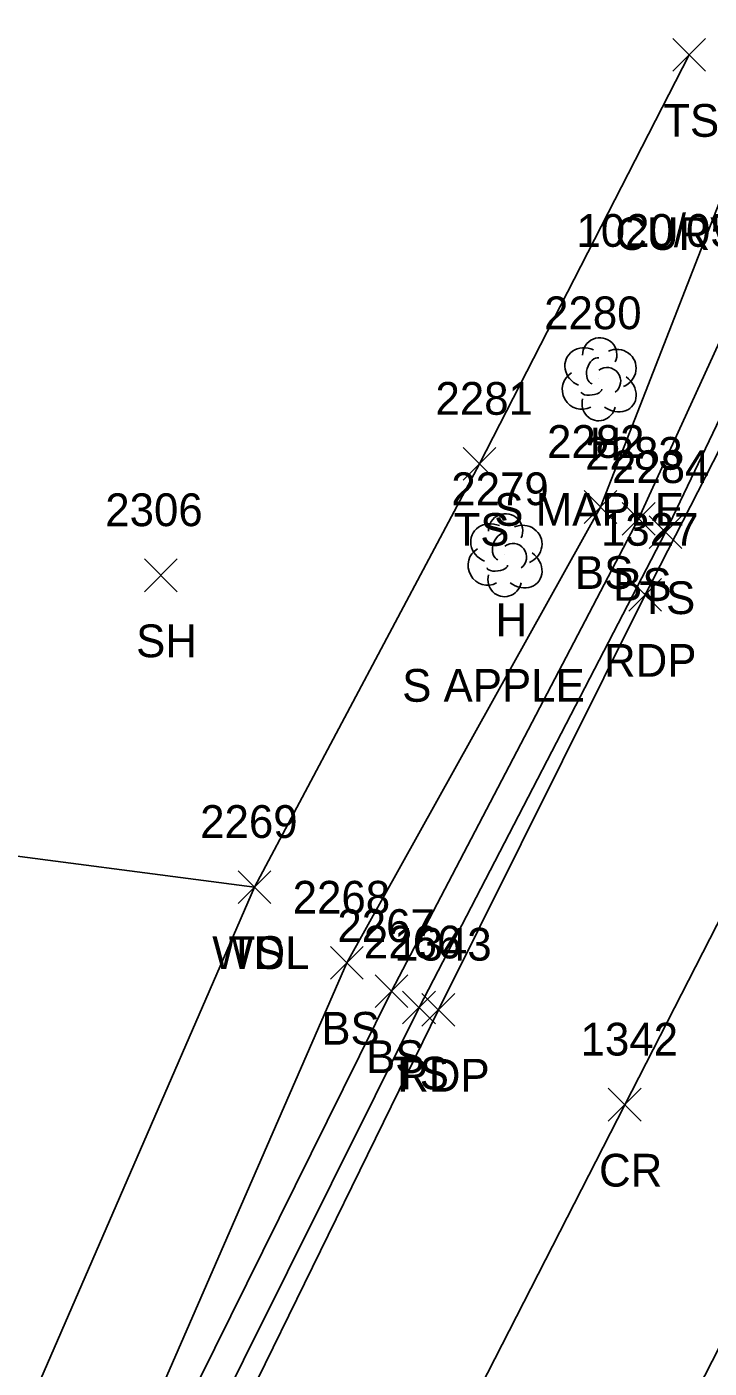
# Model space of a CAD drawing. Extents: x 1885914 to 1887218, y 756253 to 760620.
# Drawn here: x 1886645.8 to 1886687.5, y 760277.1 to 760359 of the extents above; entities that cross this region are included whole.
import ezdxf

# ---------------------------------------------------------------- set-up
doc = ezdxf.new("R2010")
doc.units = 0
for name, color, linetype in [('L_A', 7, 'Continuous'), ('L_C', 7, 'Continuous'), ('L_I', 7, 'Continuous'), ('L_TIC', 7, 'Continuous'), ('LAWA', 7, 'Continuous'), ('LELB', 7, 'Continuous'), ('LTD', 7, 'Continuous'), ('P_A', 7, 'Continuous'), ('P_I', 7, 'Continuous'), ('P_TIC', 7, 'Continuous'), ('PET', 7, 'Continuous'), ('PRC', 7, 'Continuous'), ('S_C', 7, 'Continuous')]:
    doc.layers.add(name, color=color, linetype=linetype)

msp = doc.modelspace()

# ---------------------------------------------------------------- linework, layer by layer
at = {"layer": 'L_TIC'}
for points in [[(1886685.242, 760356.287), (1886687.242, 760358.287)], [(1886687.242, 760356.287), (1886685.242, 760358.287)], [(1886672.438, 760331.318), (1886674.438, 760333.318)], [(1886674.438, 760331.318), (1886672.438, 760333.318)], [(1886679.817, 760328.686), (1886681.817, 760330.686)], [(1886681.817, 760328.686), (1886679.817, 760330.686)], [(1886682.151, 760327.963), (1886684.151, 760329.963)], [(1886684.151, 760327.963), (1886682.151, 760329.963)], [(1886683.784, 760327.15), (1886685.784, 760329.15)], [(1886685.784, 760327.15), (1886683.784, 760329.15)], [(1886652.974, 760324.518), (1886654.974, 760326.518)], [(1886654.974, 760324.518), (1886652.974, 760326.518)], [(1886658.691, 760305.487), (1886660.691, 760307.487)], [(1886660.691, 760305.487), (1886658.691, 760307.487)], [(1886658.691, 760305.487), (1886660.691, 760307.487)], [(1886660.691, 760305.487), (1886658.691, 760307.487)], [(1886664.332, 760300.863), (1886666.332, 760302.863)], [(1886666.332, 760300.863), (1886664.332, 760302.863)], [(1886667.061, 760299.134), (1886669.061, 760301.134)], [(1886669.061, 760299.134), (1886667.061, 760301.134)], [(1886668.739, 760298.131), (1886670.739, 760300.131)], [(1886670.739, 760298.131), (1886668.739, 760300.131)]]:
    msp.add_lwpolyline(points, dxfattribs=at)
at = {"layer": 'LAWA'}
msp.add_lwpolyline([(1886557.492, 760303.875), (1886591.462, 760287.384), (1886586.596, 760261.317), (1886572.395, 760231.508), (1886560.835, 760204.169), (1886553.529, 760184.951), (1886554.608, 760165.788), (1886555.431, 760150.16), (1886559.733, 760135.931), (1886571.707, 760133.875), (1886584.515, 760154.184), (1886595.308, 760177.701), (1886612.547, 760208.5), (1886627.728, 760237.63), (1886641.554, 760264.816), (1886659.691, 760306.487), (1886641.283, 760308.875), (1886618.53, 760315.267), (1886578.462, 760328.998), (1886533.456, 760348.84), (1886508.343, 760359.001)], dxfattribs=at)
at = {"layer": 'LELB'}
for points in [[(1886659.691, 760306.487), (1886673.438, 760332.318), (1886686.242, 760357.287)], [(1886566.147, 760118.03), (1886586.712, 760153.389), (1886597.757, 760175.933), (1886614.926, 760207.48), (1886633.427, 760234.813), (1886648.397, 760263.018), (1886665.332, 760301.863), (1886680.817, 760329.686), (1886690.647, 760354.868)], [(1886569.485, 760114.599), (1886588.518, 760152.373), (1886601.13, 760173.249), (1886619.202, 760206.038), (1886634.532, 760234.244), (1886649.403, 760262.458), (1886668.061, 760300.134), (1886683.151, 760328.963), (1886694.248, 760353.247)], [(1886571.834, 760112.637), (1886591.916, 760150.851), (1886603.315, 760171.698), (1886621.882, 760204.85), (1886636.208, 760233.059), (1886650.971, 760261.462), (1886669.739, 760299.131), (1886684.784, 760328.15), (1886696.366, 760352.364)]]:
    msp.add_lwpolyline(points, dxfattribs=at)
at = {"layer": 'LTD'}
for p, q in [((1886680.727, 760337.541), (1886680.727, 760337.541)), ((1886680.727, 760337.541), (1886680.727, 760337.541)), ((1886674.979, 760326.8), (1886674.979, 760326.8)), ((1886674.979, 760326.8), (1886674.979, 760326.8))]:
    msp.add_line(p, q, dxfattribs=at)
for centre in [(1886680.774, 760338.975), (1886675.025, 760328.234)]:
    msp.add_arc(centre, 1.047, 335.52715, 180.95627, dxfattribs=at)
for centre, major_axis, ratio, start_param, end_param in [((1886679.935, 760338.207), (1.21, -0.512), 0.895232, 1.570796, 4.712389), ((1886680.518, 760337.999), (-0.208, -0.792), 0.645439, 3.141593, 6.283185), ((1886681.768, 760338.124), (-1.141, -0.483), 0.949671, 1.570796, 4.712389), ((1886681.227, 760337.374), (-0.5, 0.667), 0.989748, 3.141593, 6.283185), ((1886679.644, 760336.832), (0.584, -1.042), 0.959034, 3.141593, 6.283185), ((1886681.727, 760336.708), (-1.09, 0.792), 0.841452, 1.570796, 4.712389), ((1886680.727, 760336.041), (0.265, 1.061), 0.942809, 1.570796, 4.712389), ((1886680.269, 760336.791), (-0.625, -0.083), 0.423636, 0, 3.141593), ((1886674.187, 760327.467), (1.21, -0.512), 0.895232, 1.570796, 4.712389), ((1886674.77, 760327.259), (-0.208, -0.792), 0.645439, 3.141593, 6.283185), ((1886676.02, 760327.384), (-1.141, -0.483), 0.949671, 1.570796, 4.712389), ((1886675.479, 760326.634), (-0.5, 0.667), 0.989748, 3.141593, 6.283185), ((1886673.895, 760326.092), (0.584, -1.042), 0.959034, 3.141593, 6.283185), ((1886675.979, 760325.967), (-1.09, 0.792), 0.841452, 1.570796, 4.712389), ((1886674.52, 760326.05), (-0.625, -0.083), 0.423636, 0, 3.141593), ((1886674.979, 760325.3), (0.265, 1.061), 0.942809, 1.570796, 4.712389)]:
    msp.add_ellipse(centre, major_axis=major_axis, ratio=ratio, start_param=start_param, end_param=end_param, dxfattribs=at)
at = {"layer": 'P_TIC'}
for points in [[(1886682.548, 760323.324), (1886684.548, 760325.324)], [(1886684.548, 760323.324), (1886682.548, 760325.324)], [(1886669.919, 760297.997), (1886671.919, 760299.997)], [(1886671.919, 760297.997), (1886669.919, 760299.997)], [(1886681.3, 760292.202), (1886683.3, 760294.202)], [(1886683.3, 760292.202), (1886681.3, 760294.202)]]:
    msp.add_lwpolyline(points, dxfattribs=at)
at = {"layer": 'PET'}
for points in [[(1886697.38, 760351.344), (1886683.548, 760324.324), (1886670.919, 760298.997), (1886655.54, 760267.572), (1886637.844, 760233.454), (1886621.762, 760202.258), (1886604.958, 760170.918), (1886588.135, 760139.085), (1886573.727, 760111.629), (1886569.921, 760108.658), (1886558.783, 760086.235), (1886539.061, 760048.095), (1886537.996, 760043.117), (1886529.578, 760026.839), (1886519.947, 760007.47), (1886505.21, 759975.038), (1886485.323, 759931.758)], [(1886719.61, 760339.514), (1886705.929, 760312.964), (1886693.411, 760288.801), (1886676.565, 760255.91), (1886659.381, 760222.808), (1886642.609, 760189.876), (1886625.619, 760158.68), (1886608.905, 760127.1), (1886594.007, 760097.907), (1886581.162, 760073.399), (1886568.003, 760045.025), (1886556.596, 760025.444), (1886542.605, 759998.542), (1886526.138, 759964.92), (1886507.071, 759922.754)]]:
    msp.add_lwpolyline(points, dxfattribs=at)
at = {"layer": 'PRC'}
msp.add_lwpolyline([(1886708.511, 760345.163), (1886695.269, 760318.5), (1886682.3, 760293.202), (1886665.98, 760261.316), (1886649.024, 760227.782), (1886632.442, 760196.03), (1886615.486, 760164.092), (1886599.17, 760133.157), (1886583.217, 760103.131), (1886570.574, 760078.827), (1886555.848, 760051.114), (1886540.619, 760021), (1886531.872, 760002.722), (1886516.053, 759969.427), (1886496.99, 759926.688)], dxfattribs=at)

# ---------------------------------------------------------------- texts
at = {"layer": 'L_A'}
for s, p in [('TS', (1886684.652, 760352.287)), ('H', (1886680.16, 760332.541)), ('TS', (1886671.847, 760327.318)), ('BS', (1886679.258, 760324.686)), ('BS', (1886681.592, 760323.963)), ('TS', (1886683.194, 760323.15)), ('H', (1886674.412, 760321.8)), ('SH', (1886652.462, 760320.518)), ('WDL', (1886657.109, 760301.487)), ('TS', (1886658.101, 760301.487)), ('BS', (1886663.773, 760296.863)), ('BS', (1886666.502, 760295.134)), ('TS', (1886668.149, 760294.131))]:
    msp.add_text(s, height=2, dxfattribs=at).set_placement(p)
at = {"layer": 'L_C'}
for s, p in [('S MAPLE', (1886674.333, 760328.541)), ('S APPLE', (1886668.711, 760317.8))]:
    msp.add_text(s, height=2, dxfattribs=at).set_placement(p)
at = {"layer": 'L_I'}
for s, p in [('2280', (1886677.38, 760340.541)), ('2281', (1886670.745, 760335.318)), ('2282', (1886677.558, 760332.686)), ('2283', (1886679.891, 760331.963)), ('2284', (1886681.524, 760331.15)), ('2279', (1886671.711, 760329.8)), ('2306', (1886650.58, 760328.518)), ('2269', (1886656.376, 760309.487)), ('2269', (1886656.376, 760309.487)), ('2268', (1886662.025, 760304.863)), ('2267', (1886664.754, 760303.134)), ('2266', (1886666.377, 760302.131))]:
    msp.add_text(s, height=2, dxfattribs=at).set_placement(p)
at = {"layer": 'P_A'}
for s, p in [('RDP', (1886681.036, 760319.324)), ('RDP', (1886668.407, 760293.997)), ('CR', (1886680.733, 760288.202))]:
    msp.add_text(s, height=2, dxfattribs=at).set_placement(p)
at = {"layer": 'P_I'}
for s, p in [('1327', (1886680.855, 760327.324)), ('1343', (1886668.226, 760301.997)), ('1342', (1886679.607, 760296.202))]:
    msp.add_text(s, height=2, dxfattribs=at).set_placement(p)
at = {"layer": 'S_C'}
for s, p in [('1020/0515/0080', (1886679.352, 760345.57)), ('CURVE LEFT', (1886681.725, 760345.381))]:
    msp.add_text(s, height=2, dxfattribs=at).set_placement(p)

doc.saveas('drawing.dxf')
